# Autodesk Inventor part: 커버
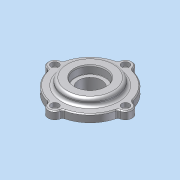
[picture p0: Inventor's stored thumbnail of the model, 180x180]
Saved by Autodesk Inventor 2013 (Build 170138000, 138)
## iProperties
Company: 한국ATC센터
Created: 2015-03
Part Number: 커버
Document SubType Name: Modeling
Designer: KYOUNG IL JANG
Density: 1 g/cm^3
Material: 일반
Author: KYOUNG IL JANG
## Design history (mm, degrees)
sketch "스케치1"
  geometry: C1 r 1.621 at (0, 6.75) reference; C2 r 1.621 at (-37, -30.25) reference; C3 r 1.621 at (0, -67.25) reference; C4 r 1.621 at (37, -30.25) reference; C5 r 10 at (0, -30.25) reference; C6 r 12 at (0, -30.25); C7 r 24.5 at (0, -30.25) reference; A1 r 3 centre (-38.77, -20.408) between (-38.239, -23.361) and (-35.862, -21.146) reference; A2 r 7 centre (-37, -30.25) between (-38.239, -23.361) and (-38.239, -37.139) reference; A3 r 3 centre (-38.77, -40.092) between (-35.862, -39.354) and (-38.239, -37.139) reference; A4 r 37 centre (0, -30.25) between (-35.862, -39.354) and (-9.104, -66.113) reference; A5 r 3 centre (-9.842, -69.02) between (-6.889, -68.489) and (-9.104, -66.113) reference; A6 r 7 centre (0, -67.25) between (-6.889, -68.489) and (6.889, -68.489) reference; A7 r 3 centre (9.842, -69.02) between (9.104, -66.112) and (6.889, -68.489) reference; A8 r 37 centre (0, -30.25) between (9.104, -66.112) and (35.863, -39.354) reference; A9 r 3 centre (38.77, -40.092) between (38.239, -37.139) and (35.863, -39.354) reference; A10 r 7 centre (37, -30.25) between (38.239, -37.139) and (38.239, -23.361) reference; A11 r 3 centre (38.77, -20.408) between (35.863, -21.146) and (38.239, -23.361) reference; A12 r 37 centre (0, -30.25) between (35.863, -21.146) and (9.104, 5.612) reference; A13 r 3 centre (9.842, 8.52) between (6.889, 7.989) and (9.104, 5.612) reference; A14 r 7 centre (0, 6.75) between (6.889, 7.989) and (-6.889, 7.989) reference; A15 r 3 centre (-9.842, 8.52) between (-9.104, 5.612) and (-6.889, 7.989) reference; A16 r 37 centre (0, -30.25) between (-9.104, 5.612) and (-35.862, -21.146) reference; 1 further point
  constraints: 1 centre point, 1 coincident
  dimensions: "d2" = 2 radial gap between concentric circles of C6 C5
extrude "돌출1" new body sketch "스케치1" distance "d0" = 8; taper "d1" = 0 deg
sketch "스케치2"
  geometry: C1 r 23.5 at (0, -30.25) reference; C2 r 12 at (0, -30.25) reference; 1 further point
extrude "돌출2" join sketch "스케치2" distance "d4" = 5; taper "d5" = 0 deg
sketch "스케치3"
  geometry: C1 r 23.5 at (0, 0) reference; C2 r 20.5 at (0, 0); 1 further point
  constraints: 1 centre point
  dimensions: "d6" = 3 radial gap between concentric circles of C2 C1
node "작업 평면1"
extrude "돌출3" join sketch "스케치3" stored distance "d7" = 5; taper "d8" = 0 deg
fillet "모깎기1" dims "d9" = 3
sketch "스케치4"
  geometry: C1 r 12 at (0, -30.25) reference; C2 r 27 at (0, -30.25); 1 further point
  constraints: 1 centre point
  dimensions: "d10" = 15 radial gap between concentric circles of C1 C2
extrude "돌출4" join sketch "스케치4" distance "d11" = 7; taper "d12" = 0 deg
fillet "모깎기2" dims "d13" = 3
chamfer "모따기1" distance "d14" = 1; stored, may be unused: second distance "d15" = 2, angle "d16" = 45 deg
node "작업점1"
  node "작업축1"
chamfer "모따기2" distance "d24" = 1; stored, may be unused: second distance "d25" = 2, angle "d26" = 45 deg
hole "구멍6" diameter "d43" = 4.5; stored, may be unused: countersink angle "d47" = 90 deg, drill point angle "d49" = 118 deg; dims "d41" = 10, "d42" = 10, "d44" = 6, "d45" = 8, "d46" = 4.4, "d48" = 8
sketch "스케치8"
  geometry: C1 r 12 at (0, 0) reference; C2 r 16 at (0, 0); 1 further point
  constraints: 1 centre point, 1 coincident
  dimensions: "d53" = 32 diameter of C2
extrude "돌출5" cut sketch "스케치8" distance "d54" = 8.3; taper "d55" = 0 deg
fillet "모깎기3" dims "d56" = 0.3
chamfer "모따기3" distance "d57" = 1.2; stored, may be unused: second distance "d58" = 2, angle "d59" = 30 deg
node "솔리드1"
pattern_circular "원형 패턴1" dims angle "d51" = 360 deg
node "참조1"
node "참조2"
